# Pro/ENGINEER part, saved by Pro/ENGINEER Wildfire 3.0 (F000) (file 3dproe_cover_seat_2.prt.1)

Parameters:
  DESCRIPTION = "NITRILE BONNET PACKING"
  MODELED_BY = "L. CONARD"
  PTC_COMMON_NAME = "NITRILE BONNET PACKING"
